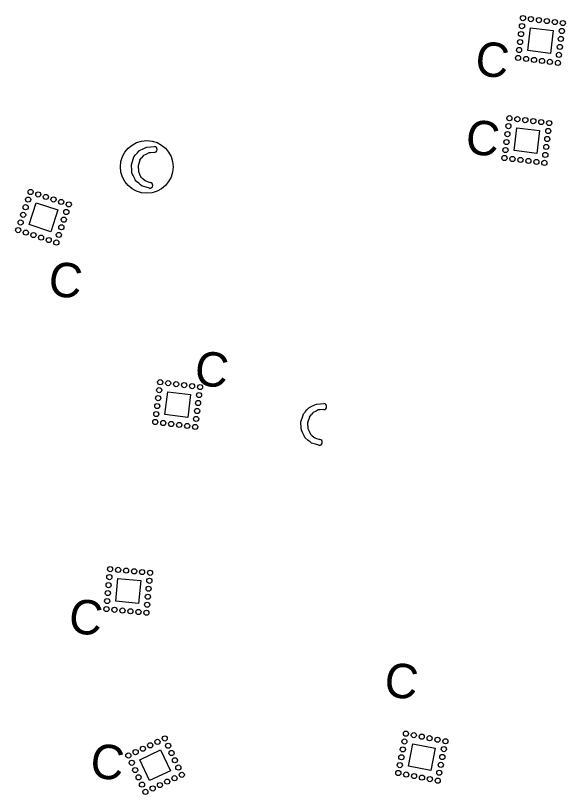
# Model space of a CAD drawing. Extents: x 2470000 to 2520000, y 340000 to 380000.
# Drawn here: x 2483351.7 to 2483591.3, y 365713.9 to 366053.6 of the extents above; entities that cross this region are included whole.
import ezdxf

# ---------------------------------------------------------------- set-up
doc = ezdxf.new("R2010")
doc.units = 0
for name, color, linetype in [('Coir Fiber Wattle with PAM Final CELL', 7, 'Continuous'), ('Prop Guardrail', 7, 'Continuous'), ('Prop Guardrail Anchor Unit CELL', 7, 'Continuous'), ('Prop Structure Anchor Unit CELL', 7, 'Continuous'), ('Scratch_Level_5', 7, 'Continuous'), ('Wattle Both CELL', 7, 'Continuous')]:
    doc.layers.add(name, color=color, linetype=linetype)

# ---------------------------------------------------------------- blocks, each defined once
blk = doc.blocks.new('C3')
at = {"layer": 'Prop Guardrail'}
blk.add_text('C', height=0.3, dxfattribs=at).set_placement((-0.161, -0.136))
blk = doc.blocks.new('C2')
at = {"layer": 'Prop Guardrail Anchor Unit CELL'}
blk.add_text('C', height=0.3, dxfattribs=at).set_placement((-0.161, -0.136))

msp = doc.modelspace()

# ---------------------------------------------------------------- linework, layer by layer
at = {"layer": 'Coir Fiber Wattle with PAM Final CELL'}
for p, q in [((2483407.3, 365992.4), (2483406.6, 365991.54)), ((2483407.3, 365992.4), (2483407.45, 365992.59)), ((2483408.75, 365993.23), (2483407.45, 365992.59)), ((2483409.74, 365993.72), (2483408.75, 365993.23)), ((2483410.53, 365993.77), (2483409.74, 365993.72)), ((2483412.08, 365993.85), (2483410.53, 365993.77)), ((2483405.86, 365990.61), (2483405.09, 365988.1)), ((2483405.86, 365990.61), (2483406.6, 365991.54)), ((2483405.08, 365988.08), (2483405.09, 365988.1)), ((2483405.08, 365988.08), (2483405.2, 365985.55)), ((2483405.2, 365985.55), (2483405.71, 365984.45)), ((2483405.71, 365984.45), (2483406.31, 365983.14)), ((2483406.31, 365983.14), (2483407.1, 365982.48)), ((2483407.1, 365982.48), (2483408.24, 365981.54)), ((2483408.56, 365981.44), (2483408.24, 365981.54)), ((2483408.56, 365981.44), (2483410.33, 365980.87))]:
    msp.add_line(p, q, dxfattribs=at)
msp.add_lwpolyline([(2483410.01, 365978.29), (2483408.52, 365978.74), (2483406.78, 365979.27), (2483406.14, 365979.8), (2483405.36, 365980.45), (2483403.98, 365981.59), (2483403.96, 365981.63), (2483403.76, 365982.02), (2483403.73, 365982.09), (2483403.31, 365982.95), (2483403.02, 365983.55), (2483402.37, 365984.86), (2483402.3, 365985.9), (2483402.13, 365988.45), (2483402.14, 365988.46), (2483402.94, 365990.97), (2483403.26, 365991.95), (2483403.99, 365992.81), (2483404.15, 365992.99), (2483404.77, 365993.72), (2483405.25, 365994.28), (2483405.36, 365994.4), (2483405.6, 365994.68), (2483405.6, 365994.69), (2483406.96, 365995.35), (2483408.17, 365995.93), (2483408.9, 365996.28), (2483410.65, 365996.41), (2483412.2, 365996.51)], dxfattribs=at)
msp.add_circle((2483408.85, 365987.61), 11.5, dxfattribs=at)
for centre, radius, start in [((2483412.04, 365995.19), 1.33, 271.8897), ((2483410.17, 365979.58), 1.3, 263.0023)]:
    msp.add_arc(centre, radius, start, 83.0023, dxfattribs=at)
at = {"layer": 'Prop Structure Anchor Unit CELL'}
for points in [[(2483417.97, 365889.5), (2483427.89, 365888.28), (2483426.68, 365878.35), (2483416.75, 365879.59)], [(2483396.27, 365808.07), (2483406.23, 365807.16), (2483405.32, 365797.2), (2483395.36, 365798.12)], [(2483405.83, 365729.04), (2483414.89, 365733.29), (2483419.13, 365724.23), (2483410.08, 365720)]]:
    msp.add_lwpolyline(points, close=True, dxfattribs=at)
for centre in [(2483414.7, 365893.7), (2483418.17, 365893.27), (2483421.65, 365892.84), (2483425.12, 365892.42), (2483414.27, 365890.22), (2483428.59, 365891.99), (2483432.07, 365891.56), (2483413.84, 365886.75), (2483431.64, 365888.09), (2483413.42, 365883.28), (2483431.21, 365884.62), (2483412.99, 365879.8), (2483430.79, 365881.14), (2483412.56, 365876.33), (2483416.04, 365875.9), (2483419.51, 365875.47), (2483430.36, 365877.67), (2483422.99, 365875.05), (2483426.46, 365874.62), (2483429.93, 365874.19), (2483392.87, 365812.16), (2483396.36, 365811.84), (2483399.84, 365811.52), (2483403.33, 365811.21), (2483406.81, 365810.89), (2483410.3, 365810.57), (2483392.55, 365808.68), (2483392.23, 365805.19), (2483409.98, 365807.08), (2483391.91, 365801.71), (2483409.66, 365803.6), (2483391.6, 365798.22), (2483409.34, 365800.11), (2483391.28, 365794.73), (2483394.76, 365794.42), (2483398.25, 365794.1), (2483401.73, 365793.78), (2483409.02, 365796.63), (2483405.22, 365793.46), (2483408.7, 365793.14), (2483413.51, 365736.8), (2483416.67, 365738.29), (2483407.17, 365733.83), (2483410.34, 365735.31), (2483418.16, 365735.12), (2483400.83, 365730.86), (2483404, 365732.34), (2483419.65, 365731.95), (2483402.32, 365727.69), (2483421.13, 365728.78), (2483422.62, 365725.61), (2483403.8, 365724.52), (2483424.11, 365722.44), (2483405.29, 365721.35), (2483417.77, 365719.47), (2483420.94, 365720.96), (2483406.78, 365718.18), (2483411.43, 365716.5), (2483414.6, 365717.98), (2483408.26, 365715.01)]:
    msp.add_circle(centre, 1.12, dxfattribs=at)
at = {"layer": 'Scratch_Level_5'}
for points in [[(2483576.07, 366048.29), (2483585.99, 366047.07), (2483584.78, 366037.14), (2483574.85, 366038.38)], [(2483570.14, 366004.65), (2483580.07, 366003.44), (2483578.85, 365993.51), (2483568.93, 365994.74)], [(2483360.64, 365971.92), (2483370.15, 365968.82), (2483367.05, 365959.31), (2483357.54, 365962.43)], [(2483524.77, 365735.99), (2483534.59, 365734.09), (2483532.69, 365724.27), (2483522.87, 365726.18)]]:
    msp.add_lwpolyline(points, close=True, dxfattribs=at)
for centre in [(2483572.8, 366052.49), (2483576.27, 366052.06), (2483572.37, 366049.01), (2483579.75, 366051.63), (2483583.22, 366051.21), (2483586.69, 366050.78), (2483590.17, 366050.35), (2483571.95, 366045.54), (2483589.74, 366046.88), (2483571.52, 366042.07), (2483589.32, 366043.41), (2483571.09, 366038.59), (2483588.89, 366039.93), (2483570.67, 366035.12), (2483588.46, 366036.46), (2483574.14, 366034.69), (2483577.61, 366034.26), (2483581.09, 366033.84), (2483584.56, 366033.41), (2483588.04, 366032.98), (2483566.87, 366008.85), (2483570.35, 366008.43), (2483573.82, 366008), (2483577.3, 366007.57), (2483566.45, 366005.38), (2483580.77, 366007.15), (2483584.24, 366006.72), (2483566.02, 366001.91), (2483583.82, 366003.25), (2483565.59, 365998.43), (2483583.39, 365999.77), (2483565.17, 365994.96), (2483582.96, 365996.3), (2483564.74, 365991.48), (2483568.21, 365991.06), (2483571.69, 365990.63), (2483582.54, 365992.82), (2483575.16, 365990.2), (2483578.64, 365989.78), (2483582.11, 365989.35), (2483358.24, 365976.67), (2483361.56, 365975.59), (2483364.89, 365974.5), (2483357.15, 365973.34), (2483368.22, 365973.41), (2483371.55, 365972.33), (2483374.87, 365971.24), (2483356.07, 365970.02), (2483373.79, 365967.92), (2483354.98, 365966.69), (2483372.7, 365964.59), (2483352.81, 365960.03), (2483353.89, 365963.36), (2483371.62, 365961.26), (2483356.14, 365958.95), (2483359.46, 365957.86), (2483362.79, 365956.78), (2483370.53, 365957.93), (2483366.12, 365955.69), (2483369.45, 365954.61), (2483521.79, 365740.4), (2483525.23, 365739.74), (2483521.13, 365736.97), (2483528.67, 365739.08), (2483532.1, 365738.41), (2483535.54, 365737.75), (2483538.98, 365737.08), (2483520.47, 365733.53), (2483538.31, 365733.65), (2483519.8, 365730.09), (2483537.65, 365730.21), (2483519.14, 365726.66), (2483536.98, 365726.77), (2483518.47, 365723.22), (2483521.91, 365722.56), (2483536.32, 365723.34), (2483525.35, 365721.89), (2483528.78, 365721.23), (2483532.22, 365720.56), (2483535.65, 365719.9)]:
    msp.add_circle(centre, 1.12, dxfattribs=at)
at = {"layer": 'Wattle Both CELL'}
for p, q in [((2483481.18, 365880.29), (2483480.48, 365879.42)), ((2483481.18, 365880.29), (2483481.33, 365880.47)), ((2483482.62, 365881.12), (2483481.33, 365880.47)), ((2483483.61, 365881.61), (2483482.62, 365881.12)), ((2483484.4, 365881.65), (2483483.61, 365881.61)), ((2483485.95, 365881.74), (2483484.4, 365881.65)), ((2483479.73, 365878.5), (2483478.96, 365875.98)), ((2483479.73, 365878.5), (2483480.48, 365879.42)), ((2483478.96, 365875.97), (2483478.96, 365875.98)), ((2483478.96, 365875.97), (2483479.08, 365873.43)), ((2483479.08, 365873.43), (2483479.58, 365872.34)), ((2483479.58, 365872.34), (2483480.19, 365871.03)), ((2483480.19, 365871.03), (2483480.98, 365870.37)), ((2483480.98, 365870.37), (2483482.12, 365869.42)), ((2483482.43, 365869.32), (2483482.12, 365869.42)), ((2483482.43, 365869.32), (2483484.2, 365868.75))]:
    msp.add_line(p, q, dxfattribs=at)
msp.add_lwpolyline([(2483483.89, 365866.18), (2483482.4, 365866.63), (2483480.66, 365867.16), (2483480.01, 365867.69), (2483479.23, 365868.33), (2483477.85, 365869.48), (2483477.83, 365869.51), (2483477.64, 365869.91), (2483477.6, 365869.98), (2483477.18, 365870.83), (2483476.89, 365871.43), (2483476.24, 365872.75), (2483476.17, 365873.79), (2483476.01, 365876.33), (2483476.01, 365876.34), (2483476.82, 365878.85), (2483477.13, 365879.83), (2483477.87, 365880.69), (2483478.02, 365880.88), (2483478.65, 365881.61), (2483479.12, 365882.16), (2483479.23, 365882.29), (2483479.47, 365882.57), (2483479.48, 365882.57), (2483480.84, 365883.23), (2483482.05, 365883.82), (2483482.78, 365884.17), (2483484.53, 365884.29), (2483486.07, 365884.4)], dxfattribs=at)
for centre, radius, start in [((2483485.91, 365883.07), 1.33, 271.8897), ((2483484.05, 365867.46), 1.3, 263.0023)]:
    msp.add_arc(centre, radius, start, 83.0023, dxfattribs=at)

# ---------------------------------------------------------------- block references
at = {"layer": 'Prop Structure Anchor Unit CELL', "xscale": 49.99999999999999, "yscale": 50.00000000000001, "rotation": -6.997703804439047}
for p in [(2483437.93, 365898.52), (2483383.08, 365790.44), (2483392.45, 365727.3)]:
    msp.add_blockref('C2', p, dxfattribs=at)
at = {"layer": 'Scratch_Level_5', "xscale": 49.99999999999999, "yscale": 50.00000000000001, "rotation": -6.997703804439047}
for p in [(2483560.21, 366033.6), (2483556.02, 365999.41), (2483374.21, 365937.49), (2483520.6, 365762.61)]:
    msp.add_blockref('C3', p, dxfattribs=at)

doc.saveas('drawing.dxf')
